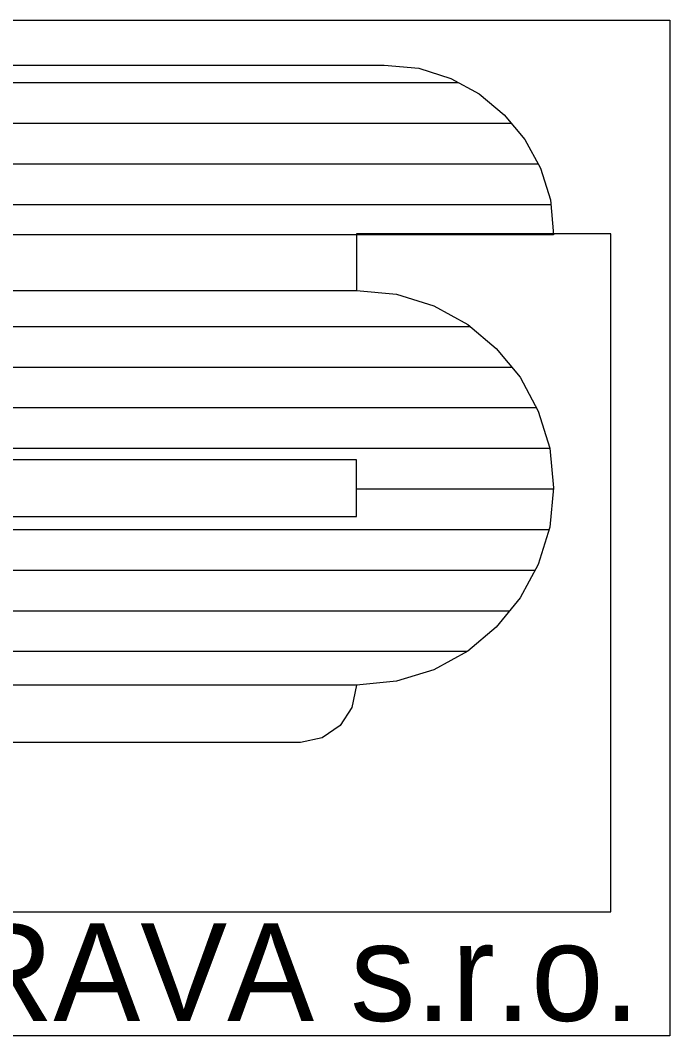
# Model space of a CAD drawing. Extents: x -449577 to -425530, y -1150048 to -1121091.
# Drawn here: x -435009.8 to -434926.6, y -1142558.3 to -1142428.3 of the extents above; entities that cross this region are included whole.
import ezdxf

# ---------------------------------------------------------------- set-up
doc = ezdxf.new("R2010")
doc.units = 0
doc.layers.add('Vrstva 1', color=7, linetype='Continuous')

msp = doc.modelspace()

# ---------------------------------------------------------------- linework, layer by layer
at = {"layer": 'Vrstva 1'}
for p, q in [((-435063.83, -1142436.3), (-434953.68, -1142436.3)), ((-435063.83, -1142436.3), (-434953.68, -1142436.3)), ((-435063.83, -1142436.3), (-434953.68, -1142436.3)), ((-435063.83, -1142436.3), (-434953.68, -1142436.3)), ((-435063.83, -1142436.3), (-434953.68, -1142436.3)), ((-435063.83, -1142436.3), (-434953.68, -1142436.3)), ((-435063.83, -1142436.3), (-434953.68, -1142436.3)), ((-435063.83, -1142436.3), (-434953.68, -1142436.3)), ((-435071.45, -1142441.51), (-434946.94, -1142441.51)), ((-435071.45, -1142441.51), (-434946.94, -1142441.51)), ((-435071.45, -1142441.51), (-434946.94, -1142441.51)), ((-435071.45, -1142441.51), (-434946.94, -1142441.51)), ((-435071.45, -1142441.51), (-434946.94, -1142441.51)), ((-435071.45, -1142441.51), (-434946.94, -1142441.51)), ((-435071.45, -1142441.51), (-434946.94, -1142441.51)), ((-435071.45, -1142441.51), (-434946.94, -1142441.51)), ((-435075.63, -1142446.71), (-434943.5, -1142446.71)), ((-435075.63, -1142446.71), (-434943.5, -1142446.71)), ((-435075.63, -1142446.71), (-434943.5, -1142446.71)), ((-435075.63, -1142446.71), (-434943.5, -1142446.71)), ((-435075.63, -1142446.71), (-434943.5, -1142446.71)), ((-435075.63, -1142446.71), (-434943.5, -1142446.71)), ((-435075.63, -1142446.71), (-434943.5, -1142446.71)), ((-435075.63, -1142446.71), (-434943.5, -1142446.71)), ((-435077.9, -1142451.91), (-434941.87, -1142451.91)), ((-435077.9, -1142451.91), (-434941.87, -1142451.91)), ((-435077.9, -1142451.91), (-434941.87, -1142451.91)), ((-435077.9, -1142451.91), (-434941.87, -1142451.91)), ((-435077.9, -1142451.91), (-434941.87, -1142451.91)), ((-435077.9, -1142451.91), (-434941.87, -1142451.91)), ((-435077.9, -1142451.91), (-434941.87, -1142451.91)), ((-435077.9, -1142451.91), (-434941.87, -1142451.91)), ((-435077.41, -1142467.51), (-434952.23, -1142467.51)), ((-435077.41, -1142467.51), (-434952.23, -1142467.51)), ((-435077.41, -1142467.51), (-434952.23, -1142467.51)), ((-435077.41, -1142467.51), (-434952.23, -1142467.51)), ((-435077.41, -1142467.51), (-434952.23, -1142467.51)), ((-435077.41, -1142467.51), (-434952.23, -1142467.51)), ((-435077.41, -1142467.51), (-434952.23, -1142467.51)), ((-435077.41, -1142467.51), (-434952.23, -1142467.51)), ((-435074.91, -1142472.71), (-434946.87, -1142472.71)), ((-435074.91, -1142472.71), (-434946.87, -1142472.71)), ((-435074.91, -1142472.71), (-434946.87, -1142472.71)), ((-435074.91, -1142472.71), (-434946.87, -1142472.71)), ((-435074.91, -1142472.71), (-434946.87, -1142472.71)), ((-435074.91, -1142472.71), (-434946.87, -1142472.71)), ((-435074.91, -1142472.71), (-434946.87, -1142472.71)), ((-435074.91, -1142472.71), (-434946.87, -1142472.71)), ((-435070.54, -1142477.91), (-434943.74, -1142477.91)), ((-435070.54, -1142477.91), (-434943.74, -1142477.91)), ((-435070.54, -1142477.91), (-434943.74, -1142477.91)), ((-435070.54, -1142477.91), (-434943.74, -1142477.91)), ((-435070.54, -1142477.91), (-434943.74, -1142477.91)), ((-435070.54, -1142477.91), (-434943.74, -1142477.91)), ((-435070.54, -1142477.91), (-434943.74, -1142477.91)), ((-435070.54, -1142477.91), (-434943.74, -1142477.91)), ((-435061.88, -1142483.1), (-434942.02, -1142483.1)), ((-435061.88, -1142483.1), (-434942.02, -1142483.1)), ((-435061.88, -1142483.1), (-434942.02, -1142483.1)), ((-435061.88, -1142483.1), (-434942.02, -1142483.1)), ((-435061.88, -1142483.1), (-434942.02, -1142483.1)), ((-435061.88, -1142483.1), (-434942.02, -1142483.1)), ((-435061.88, -1142483.1), (-434942.02, -1142483.1)), ((-435061.88, -1142483.1), (-434942.02, -1142483.1)), ((-434966.79, -1142488.3), (-434941.53, -1142488.3)), ((-434966.79, -1142488.3), (-434941.53, -1142488.3)), ((-434966.79, -1142488.3), (-434941.53, -1142488.3)), ((-434966.79, -1142488.3), (-434941.53, -1142488.3)), ((-434966.79, -1142488.3), (-434941.53, -1142488.3)), ((-434966.79, -1142488.3), (-434941.53, -1142488.3)), ((-434966.79, -1142488.3), (-434941.53, -1142488.3)), ((-434966.79, -1142488.3), (-434941.53, -1142488.3)), ((-435078.88, -1142493.51), (-434942.11, -1142493.51)), ((-435078.88, -1142493.51), (-434942.11, -1142493.51)), ((-435078.88, -1142493.51), (-434942.11, -1142493.51)), ((-435078.88, -1142493.51), (-434942.11, -1142493.51)), ((-435078.88, -1142493.51), (-434942.11, -1142493.51)), ((-435078.88, -1142493.51), (-434942.11, -1142493.51)), ((-435078.88, -1142493.51), (-434942.11, -1142493.51)), ((-435078.88, -1142493.51), (-434942.11, -1142493.51)), ((-435078.88, -1142498.71), (-434943.89, -1142498.71)), ((-435078.88, -1142498.71), (-434943.89, -1142498.71)), ((-435078.88, -1142498.71), (-434943.89, -1142498.71)), ((-435078.88, -1142498.71), (-434943.89, -1142498.71)), ((-435078.88, -1142498.71), (-434943.89, -1142498.71)), ((-435078.88, -1142498.71), (-434943.89, -1142498.71)), ((-435078.88, -1142498.71), (-434943.89, -1142498.71)), ((-435078.88, -1142498.71), (-434943.89, -1142498.71)), ((-435078.88, -1142503.91), (-434947.14, -1142503.91)), ((-435078.88, -1142503.91), (-434947.14, -1142503.91)), ((-435078.88, -1142503.91), (-434947.14, -1142503.91)), ((-435078.88, -1142503.91), (-434947.14, -1142503.91)), ((-435078.88, -1142503.91), (-434947.14, -1142503.91)), ((-435078.88, -1142503.91), (-434947.14, -1142503.91)), ((-435078.88, -1142503.91), (-434947.14, -1142503.91)), ((-435078.88, -1142503.91), (-434947.14, -1142503.91)), ((-435078.88, -1142509.1), (-434952.56, -1142509.1)), ((-435078.88, -1142509.1), (-434952.56, -1142509.1)), ((-435078.88, -1142509.1), (-434952.56, -1142509.1)), ((-435078.88, -1142509.1), (-434952.56, -1142509.1)), ((-435078.88, -1142509.1), (-434952.56, -1142509.1)), ((-435078.88, -1142509.1), (-434952.56, -1142509.1)), ((-435078.88, -1142509.1), (-434952.56, -1142509.1)), ((-435078.88, -1142509.1), (-434952.56, -1142509.1))]:
    msp.add_line(p, q, dxfattribs=at)
for points in [[(-435093.04, -1142527.12), (-435093.04, -1142428.32), (-434926.64, -1142428.32), (-434926.64, -1142558.32), (-435061.84, -1142558.32)], [(-435093.04, -1142527.12), (-435093.04, -1142428.32), (-434926.64, -1142428.32), (-434926.64, -1142558.32), (-435061.84, -1142558.32)], [(-435093.04, -1142527.12), (-435093.04, -1142428.32), (-434926.64, -1142428.32), (-434926.64, -1142558.32), (-435061.84, -1142558.32)], [(-435093.04, -1142527.12), (-435093.04, -1142428.32), (-434926.64, -1142428.32), (-434926.64, -1142558.32), (-435061.84, -1142558.32)], [(-435093.04, -1142527.12), (-435093.04, -1142428.32), (-434926.64, -1142428.32), (-434926.64, -1142558.32), (-435061.84, -1142558.32)], [(-435093.04, -1142527.12), (-435093.04, -1142428.32), (-434926.64, -1142428.32), (-434926.64, -1142558.32), (-435061.84, -1142558.32)], [(-435093.04, -1142527.12), (-435093.04, -1142428.32), (-434926.64, -1142428.32), (-434926.64, -1142558.32), (-435061.84, -1142558.32)], [(-435093.04, -1142527.12), (-435093.04, -1142428.32), (-434926.64, -1142428.32), (-434926.64, -1142558.32), (-435061.84, -1142558.32)], [(-435053.6, -1142434.07), (-434963.22, -1142434.07), (-434958.77, -1142434.46), (-434954.7, -1142435.75), (-434951.04, -1142437.73), (-434947.87, -1142440.41), (-434945.19, -1142443.58), (-434943.2, -1142447.24), (-434941.92, -1142451.31), (-434941.52, -1142455.77), (-434966.79, -1142455.77)], [(-435053.6, -1142434.07), (-434963.22, -1142434.07), (-434958.77, -1142434.46), (-434954.7, -1142435.75), (-434951.04, -1142437.73), (-434947.87, -1142440.41), (-434945.19, -1142443.58), (-434943.2, -1142447.24), (-434941.92, -1142451.31), (-434941.52, -1142455.77), (-434966.79, -1142455.77)], [(-435053.6, -1142434.07), (-434963.22, -1142434.07), (-434958.77, -1142434.46), (-434954.7, -1142435.75), (-434951.04, -1142437.73), (-434947.87, -1142440.41), (-434945.19, -1142443.58), (-434943.2, -1142447.24), (-434941.92, -1142451.31), (-434941.52, -1142455.77), (-434966.79, -1142455.77)], [(-435053.6, -1142434.07), (-434963.22, -1142434.07), (-434958.77, -1142434.46), (-434954.7, -1142435.75), (-434951.04, -1142437.73), (-434947.87, -1142440.41), (-434945.19, -1142443.58), (-434943.2, -1142447.24), (-434941.92, -1142451.31), (-434941.52, -1142455.77), (-434966.79, -1142455.77)], [(-435053.6, -1142434.07), (-434963.22, -1142434.07), (-434958.77, -1142434.46), (-434954.7, -1142435.75), (-434951.04, -1142437.73), (-434947.87, -1142440.41), (-434945.19, -1142443.58), (-434943.2, -1142447.24), (-434941.92, -1142451.31), (-434941.52, -1142455.77), (-434966.79, -1142455.77)], [(-435053.6, -1142434.07), (-434963.22, -1142434.07), (-434958.77, -1142434.46), (-434954.7, -1142435.75), (-434951.04, -1142437.73), (-434947.87, -1142440.41), (-434945.19, -1142443.58), (-434943.2, -1142447.24), (-434941.92, -1142451.31), (-434941.52, -1142455.77), (-434966.79, -1142455.77)], [(-435053.6, -1142434.07), (-434963.22, -1142434.07), (-434958.77, -1142434.46), (-434954.7, -1142435.75), (-434951.04, -1142437.73), (-434947.87, -1142440.41), (-434945.19, -1142443.58), (-434943.2, -1142447.24), (-434941.92, -1142451.31), (-434941.52, -1142455.77), (-434966.79, -1142455.77)], [(-435053.6, -1142434.07), (-434963.22, -1142434.07), (-434958.77, -1142434.46), (-434954.7, -1142435.75), (-434951.04, -1142437.73), (-434947.87, -1142440.41), (-434945.19, -1142443.58), (-434943.2, -1142447.24), (-434941.92, -1142451.31), (-434941.52, -1142455.77), (-434966.79, -1142455.77)], [(-434966.79, -1142455.77), (-435053.6, -1142455.77)], [(-434966.79, -1142455.77), (-435053.6, -1142455.77)], [(-434966.79, -1142455.77), (-435053.6, -1142455.77)], [(-434966.79, -1142455.77), (-435053.6, -1142455.77)], [(-434966.79, -1142455.77), (-435053.6, -1142455.77)], [(-434966.79, -1142455.77), (-435053.6, -1142455.77)], [(-434966.79, -1142455.77), (-435053.6, -1142455.77)], [(-434966.79, -1142455.77), (-435053.6, -1142455.77)], [(-434934.19, -1142542.48), (-434934.19, -1142455.67), (-434941.52, -1142455.67), (-434966.79, -1142455.67), (-434966.79, -1142462.9), (-434961.64, -1142463.4), (-434956.88, -1142464.88), (-434952.52, -1142467.26), (-434948.86, -1142470.34), (-434945.78, -1142474), (-434943.51, -1142478.36), (-434942.02, -1142483.12), (-434941.52, -1142488.18), (-434942.02, -1142493.23), (-434943.51, -1142497.99), (-434945.78, -1142502.25), (-434948.86, -1142506.01), (-434952.52, -1142509.08), (-434956.88, -1142511.46), (-434961.64, -1142512.95), (-434966.79, -1142513.44), (-434967.38, -1142516.32), (-434968.87, -1142518.6), (-434971.15, -1142520.18), (-434973.93, -1142520.78), (-435046.37, -1142520.78)], [(-434934.19, -1142542.48), (-434934.19, -1142455.67), (-434941.52, -1142455.67), (-434966.79, -1142455.67), (-434966.79, -1142462.9), (-434961.64, -1142463.4), (-434956.88, -1142464.88), (-434952.52, -1142467.26), (-434948.86, -1142470.34), (-434945.78, -1142474), (-434943.51, -1142478.36), (-434942.02, -1142483.12), (-434941.52, -1142488.18), (-434942.02, -1142493.23), (-434943.51, -1142497.99), (-434945.78, -1142502.25), (-434948.86, -1142506.01), (-434952.52, -1142509.08), (-434956.88, -1142511.46), (-434961.64, -1142512.95), (-434966.79, -1142513.44), (-434967.38, -1142516.32), (-434968.87, -1142518.6), (-434971.15, -1142520.18), (-434973.93, -1142520.78), (-435046.37, -1142520.78)], [(-434934.19, -1142542.48), (-434934.19, -1142455.67), (-434941.52, -1142455.67), (-434966.79, -1142455.67), (-434966.79, -1142462.9), (-434961.64, -1142463.4), (-434956.88, -1142464.88), (-434952.52, -1142467.26), (-434948.86, -1142470.34), (-434945.78, -1142474), (-434943.51, -1142478.36), (-434942.02, -1142483.12), (-434941.52, -1142488.18), (-434942.02, -1142493.23), (-434943.51, -1142497.99), (-434945.78, -1142502.25), (-434948.86, -1142506.01), (-434952.52, -1142509.08), (-434956.88, -1142511.46), (-434961.64, -1142512.95), (-434966.79, -1142513.44), (-434967.38, -1142516.32), (-434968.87, -1142518.6), (-434971.15, -1142520.18), (-434973.93, -1142520.78), (-435046.37, -1142520.78)], [(-434934.19, -1142542.48), (-434934.19, -1142455.67), (-434941.52, -1142455.67), (-434966.79, -1142455.67), (-434966.79, -1142462.9), (-434961.64, -1142463.4), (-434956.88, -1142464.88), (-434952.52, -1142467.26), (-434948.86, -1142470.34), (-434945.78, -1142474), (-434943.51, -1142478.36), (-434942.02, -1142483.12), (-434941.52, -1142488.18), (-434942.02, -1142493.23), (-434943.51, -1142497.99), (-434945.78, -1142502.25), (-434948.86, -1142506.01), (-434952.52, -1142509.08), (-434956.88, -1142511.46), (-434961.64, -1142512.95), (-434966.79, -1142513.44), (-434967.38, -1142516.32), (-434968.87, -1142518.6), (-434971.15, -1142520.18), (-434973.93, -1142520.78), (-435046.37, -1142520.78)], [(-434934.19, -1142542.48), (-434934.19, -1142455.67), (-434941.52, -1142455.67), (-434966.79, -1142455.67), (-434966.79, -1142462.9), (-434961.64, -1142463.4), (-434956.88, -1142464.88), (-434952.52, -1142467.26), (-434948.86, -1142470.34), (-434945.78, -1142474), (-434943.51, -1142478.36), (-434942.02, -1142483.12), (-434941.52, -1142488.18), (-434942.02, -1142493.23), (-434943.51, -1142497.99), (-434945.78, -1142502.25), (-434948.86, -1142506.01), (-434952.52, -1142509.08), (-434956.88, -1142511.46), (-434961.64, -1142512.95), (-434966.79, -1142513.44), (-434967.38, -1142516.32), (-434968.87, -1142518.6), (-434971.15, -1142520.18), (-434973.93, -1142520.78), (-435046.37, -1142520.78)], [(-434934.19, -1142542.48), (-434934.19, -1142455.67), (-434941.52, -1142455.67), (-434966.79, -1142455.67), (-434966.79, -1142462.9), (-434961.64, -1142463.4), (-434956.88, -1142464.88), (-434952.52, -1142467.26), (-434948.86, -1142470.34), (-434945.78, -1142474), (-434943.51, -1142478.36), (-434942.02, -1142483.12), (-434941.52, -1142488.18), (-434942.02, -1142493.23), (-434943.51, -1142497.99), (-434945.78, -1142502.25), (-434948.86, -1142506.01), (-434952.52, -1142509.08), (-434956.88, -1142511.46), (-434961.64, -1142512.95), (-434966.79, -1142513.44), (-434967.38, -1142516.32), (-434968.87, -1142518.6), (-434971.15, -1142520.18), (-434973.93, -1142520.78), (-435046.37, -1142520.78)], [(-434934.19, -1142542.48), (-434934.19, -1142455.67), (-434941.52, -1142455.67), (-434966.79, -1142455.67), (-434966.79, -1142462.9), (-434961.64, -1142463.4), (-434956.88, -1142464.88), (-434952.52, -1142467.26), (-434948.86, -1142470.34), (-434945.78, -1142474), (-434943.51, -1142478.36), (-434942.02, -1142483.12), (-434941.52, -1142488.18), (-434942.02, -1142493.23), (-434943.51, -1142497.99), (-434945.78, -1142502.25), (-434948.86, -1142506.01), (-434952.52, -1142509.08), (-434956.88, -1142511.46), (-434961.64, -1142512.95), (-434966.79, -1142513.44), (-434967.38, -1142516.32), (-434968.87, -1142518.6), (-434971.15, -1142520.18), (-434973.93, -1142520.78), (-435046.37, -1142520.78)], [(-434934.19, -1142542.48), (-434934.19, -1142455.67), (-434941.52, -1142455.67), (-434966.79, -1142455.67), (-434966.79, -1142462.9), (-434961.64, -1142463.4), (-434956.88, -1142464.88), (-434952.52, -1142467.26), (-434948.86, -1142470.34), (-434945.78, -1142474), (-434943.51, -1142478.36), (-434942.02, -1142483.12), (-434941.52, -1142488.18), (-434942.02, -1142493.23), (-434943.51, -1142497.99), (-434945.78, -1142502.25), (-434948.86, -1142506.01), (-434952.52, -1142509.08), (-434956.88, -1142511.46), (-434961.64, -1142512.95), (-434966.79, -1142513.44), (-434967.38, -1142516.32), (-434968.87, -1142518.6), (-434971.15, -1142520.18), (-434973.93, -1142520.78), (-435046.37, -1142520.78)], [(-435053.6, -1142462.9), (-434966.79, -1142462.9), (-434961.64, -1142463.4), (-434956.88, -1142464.88), (-434952.52, -1142467.26), (-434948.86, -1142470.34), (-434945.78, -1142474), (-434943.51, -1142478.36), (-434942.02, -1142483.12), (-434941.52, -1142488.18), (-434942.02, -1142493.23), (-434943.51, -1142497.99), (-434945.78, -1142502.25), (-434948.86, -1142506.01), (-434952.52, -1142509.08), (-434956.88, -1142511.46), (-434961.64, -1142512.95), (-434966.79, -1142513.44), (-435053.6, -1142513.44)], [(-435053.6, -1142462.9), (-434966.79, -1142462.9), (-434961.64, -1142463.4), (-434956.88, -1142464.88), (-434952.52, -1142467.26), (-434948.86, -1142470.34), (-434945.78, -1142474), (-434943.51, -1142478.36), (-434942.02, -1142483.12), (-434941.52, -1142488.18), (-434942.02, -1142493.23), (-434943.51, -1142497.99), (-434945.78, -1142502.25), (-434948.86, -1142506.01), (-434952.52, -1142509.08), (-434956.88, -1142511.46), (-434961.64, -1142512.95), (-434966.79, -1142513.44), (-435053.6, -1142513.44)], [(-435053.6, -1142462.9), (-434966.79, -1142462.9), (-434961.64, -1142463.4), (-434956.88, -1142464.88), (-434952.52, -1142467.26), (-434948.86, -1142470.34), (-434945.78, -1142474), (-434943.51, -1142478.36), (-434942.02, -1142483.12), (-434941.52, -1142488.18), (-434942.02, -1142493.23), (-434943.51, -1142497.99), (-434945.78, -1142502.25), (-434948.86, -1142506.01), (-434952.52, -1142509.08), (-434956.88, -1142511.46), (-434961.64, -1142512.95), (-434966.79, -1142513.44), (-435053.6, -1142513.44)], [(-435053.6, -1142462.9), (-434966.79, -1142462.9), (-434961.64, -1142463.4), (-434956.88, -1142464.88), (-434952.52, -1142467.26), (-434948.86, -1142470.34), (-434945.78, -1142474), (-434943.51, -1142478.36), (-434942.02, -1142483.12), (-434941.52, -1142488.18), (-434942.02, -1142493.23), (-434943.51, -1142497.99), (-434945.78, -1142502.25), (-434948.86, -1142506.01), (-434952.52, -1142509.08), (-434956.88, -1142511.46), (-434961.64, -1142512.95), (-434966.79, -1142513.44), (-435053.6, -1142513.44)], [(-435053.6, -1142462.9), (-434966.79, -1142462.9), (-434961.64, -1142463.4), (-434956.88, -1142464.88), (-434952.52, -1142467.26), (-434948.86, -1142470.34), (-434945.78, -1142474), (-434943.51, -1142478.36), (-434942.02, -1142483.12), (-434941.52, -1142488.18), (-434942.02, -1142493.23), (-434943.51, -1142497.99), (-434945.78, -1142502.25), (-434948.86, -1142506.01), (-434952.52, -1142509.08), (-434956.88, -1142511.46), (-434961.64, -1142512.95), (-434966.79, -1142513.44), (-435053.6, -1142513.44)], [(-435053.6, -1142462.9), (-434966.79, -1142462.9), (-434961.64, -1142463.4), (-434956.88, -1142464.88), (-434952.52, -1142467.26), (-434948.86, -1142470.34), (-434945.78, -1142474), (-434943.51, -1142478.36), (-434942.02, -1142483.12), (-434941.52, -1142488.18), (-434942.02, -1142493.23), (-434943.51, -1142497.99), (-434945.78, -1142502.25), (-434948.86, -1142506.01), (-434952.52, -1142509.08), (-434956.88, -1142511.46), (-434961.64, -1142512.95), (-434966.79, -1142513.44), (-435053.6, -1142513.44)], [(-435053.6, -1142462.9), (-434966.79, -1142462.9), (-434961.64, -1142463.4), (-434956.88, -1142464.88), (-434952.52, -1142467.26), (-434948.86, -1142470.34), (-434945.78, -1142474), (-434943.51, -1142478.36), (-434942.02, -1142483.12), (-434941.52, -1142488.18), (-434942.02, -1142493.23), (-434943.51, -1142497.99), (-434945.78, -1142502.25), (-434948.86, -1142506.01), (-434952.52, -1142509.08), (-434956.88, -1142511.46), (-434961.64, -1142512.95), (-434966.79, -1142513.44), (-435053.6, -1142513.44)], [(-435053.6, -1142462.9), (-434966.79, -1142462.9), (-434961.64, -1142463.4), (-434956.88, -1142464.88), (-434952.52, -1142467.26), (-434948.86, -1142470.34), (-434945.78, -1142474), (-434943.51, -1142478.36), (-434942.02, -1142483.12), (-434941.52, -1142488.18), (-434942.02, -1142493.23), (-434943.51, -1142497.99), (-434945.78, -1142502.25), (-434948.86, -1142506.01), (-434952.52, -1142509.08), (-434956.88, -1142511.46), (-434961.64, -1142512.95), (-434966.79, -1142513.44), (-435053.6, -1142513.44)], [(-435053.6, -1142491.84), (-434966.79, -1142491.84), (-434966.79, -1142484.61), (-435053.6, -1142484.61)], [(-435053.6, -1142491.84), (-434966.79, -1142491.84), (-434966.79, -1142484.61), (-435053.6, -1142484.61)], [(-435053.6, -1142491.84), (-434966.79, -1142491.84), (-434966.79, -1142484.61), (-435053.6, -1142484.61)], [(-435053.6, -1142491.84), (-434966.79, -1142491.84), (-434966.79, -1142484.61), (-435053.6, -1142484.61)], [(-435053.6, -1142491.84), (-434966.79, -1142491.84), (-434966.79, -1142484.61), (-435053.6, -1142484.61)], [(-435053.6, -1142491.84), (-434966.79, -1142491.84), (-434966.79, -1142484.61), (-435053.6, -1142484.61)], [(-435053.6, -1142491.84), (-434966.79, -1142491.84), (-434966.79, -1142484.61), (-435053.6, -1142484.61)], [(-435053.6, -1142491.84), (-434966.79, -1142491.84), (-434966.79, -1142484.61), (-435053.6, -1142484.61)], [(-435060.74, -1142542.48), (-434934.19, -1142542.48)], [(-435060.74, -1142542.48), (-434934.19, -1142542.48)], [(-435060.74, -1142542.48), (-434934.19, -1142542.48)], [(-435060.74, -1142542.48), (-434934.19, -1142542.48)], [(-435060.74, -1142542.48), (-434934.19, -1142542.48)], [(-435060.74, -1142542.48), (-434934.19, -1142542.48)], [(-435060.74, -1142542.48), (-434934.19, -1142542.48)], [(-435060.74, -1142542.48), (-434934.19, -1142542.48)]]:
    msp.add_lwpolyline(points, dxfattribs=at)

# ---------------------------------------------------------------- texts
msp.add_text('OSTRAVA s.r.o.', height=12.48, dxfattribs=at).set_placement((-435051.96, -1142556.42))
msp.add_text('OSTRAVA s.r.o.', height=12.48, dxfattribs=at).set_placement((-435051.96, -1142556.42))
msp.add_text('OSTRAVA s.r.o.', height=12.48, dxfattribs=at).set_placement((-435051.96, -1142556.42))
msp.add_text('OSTRAVA s.r.o.', height=12.48, dxfattribs=at).set_placement((-435051.96, -1142556.42))
msp.add_text('OSTRAVA s.r.o.', height=12.48, dxfattribs=at).set_placement((-435051.96, -1142556.42))
msp.add_text('OSTRAVA s.r.o.', height=12.48, dxfattribs=at).set_placement((-435051.96, -1142556.42))
msp.add_text('OSTRAVA s.r.o.', height=12.48, dxfattribs=at).set_placement((-435051.96, -1142556.42))
msp.add_text('OSTRAVA s.r.o.', height=12.48, dxfattribs=at).set_placement((-435051.96, -1142556.42))

doc.saveas('drawing.dxf')
